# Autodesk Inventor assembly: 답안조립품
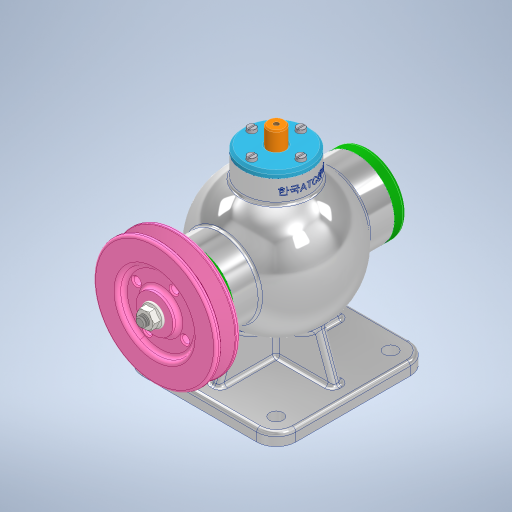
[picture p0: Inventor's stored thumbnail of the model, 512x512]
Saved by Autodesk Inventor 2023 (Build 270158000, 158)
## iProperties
Created: 2023-07
Part Number: 답안조립품
Document SubType Name: Assembly
Designer: Owner
Author: Owner
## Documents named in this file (15)
- C:\Users\Owner\Desktop\730711V1002\답안조립품.iam
- C:\Users\Owner\Desktop\730711V1002\본체.ipt
- C:\Users\Owner\Desktop\730711V1002\뒤커버.ipt
- C:\Users\Owner\Desktop\730711V1002\앞커버.ipt
- C:\Users\Owner\Desktop\730711V1002\베어링- 6202.ipt
- KS B 2023 - 6202 - 15 x 35 x 11 - 7.8.ipt
- C:\Users\Owner\Desktop\730711V1002\칼라.ipt
- C:\Users\Owner\Desktop\730711V1002\편심축.ipt
- C:\Users\Owner\Desktop\730711V1002\키 4 x 4 x 12.ipt
- C:\Users\Owner\Desktop\730711V1002\볼트 M4 x 16.ipt
- C:\Users\Owner\Desktop\730711V1002\상부커버.ipt
- C:\Users\Owner\Desktop\730711V1002\볼트 M4 x 12.ipt
- C:\Users\Owner\Desktop\730711V1002\슬라이드.ipt
- C:\Users\Owner\Desktop\730711V1002\V-벨트풀리.ipt
- C:\Users\Owner\Desktop\730711V1002\너트 M8.ipt
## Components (15 placed, 4 different names)
1. KS B 2023 - 6202 - 15 x 35 x 11 - 7.8:4
2. KS B 2023 - 6202 - 15 x 35 x 11 - 7.8:5
3. ISO 4762 M4 x 16:1
4. ISO 4762 M4 x 16:2
5. ISO 4762 M4 x 16:3
6. ISO 4762 M4 x 16:4
7. ISO 4762 M4 x 16:5
8. KS B 1021 - 에 따름 ISO 1207 - 미터 A  M 4 x 12:1
9. KS B 1021 - 에 따름 ISO 1207 - 미터 A  M 4 x 12:2
10. KS B 1021 - 에 따름 ISO 1207 - 미터 A  M 4 x 12:3
11. KS B 1021 - 에 따름 ISO 1207 - 미터 A  M 4 x 12:4
12. ISO 4762 M4 x 16:6
13. ISO 4762 M4 x 16:7
14. ISO 4762 M4 x 16:8
15. V-벨트풀리:1
